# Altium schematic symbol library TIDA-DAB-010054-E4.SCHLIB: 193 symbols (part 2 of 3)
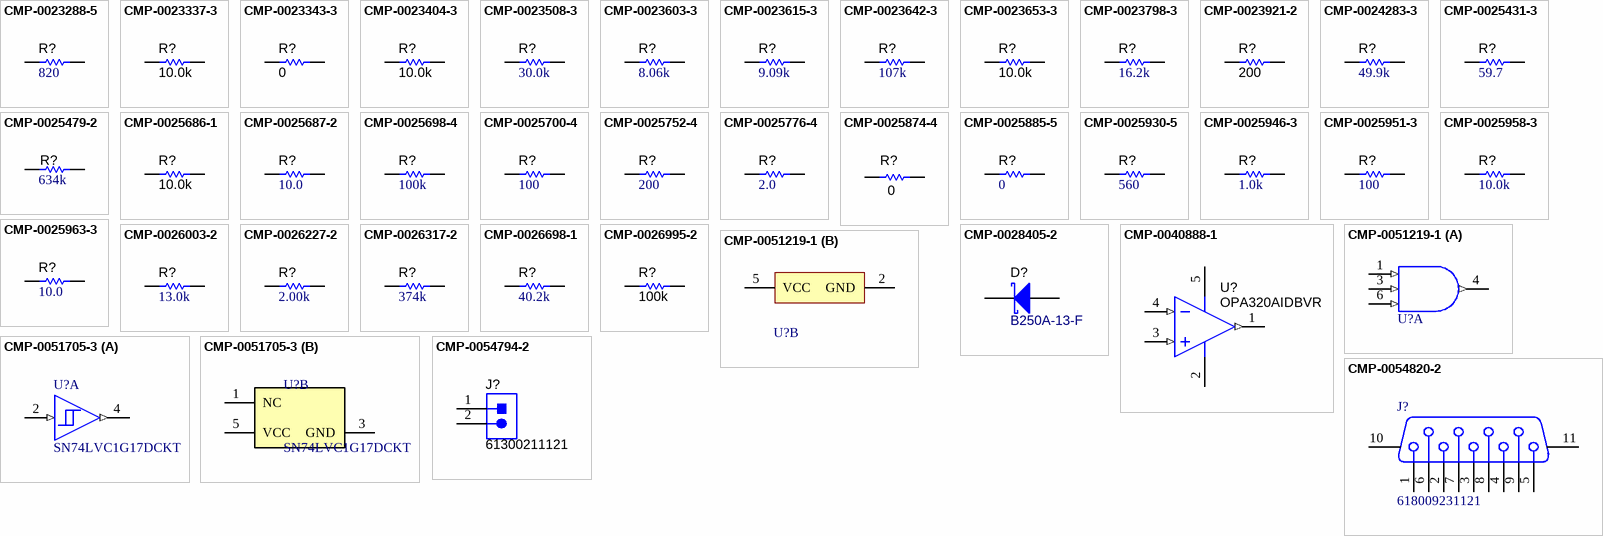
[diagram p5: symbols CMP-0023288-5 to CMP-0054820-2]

## CMP-0023615-3
designator R?, comment ValueDisplayed: 9.09k  (hidden comment: RG1608P-9091-B-T5)
RES, 9.09 k, 0.1%, 0.1 W, 0603; Manufacturer: Susumu Co Ltd; Power_W: 100mW; TempCo: 25 ppm/C; Value_Code: 9k09; U/M: EA; Value: 9.09k; EIA_Code: E192; SizeX_mm: 1.6; SizeY_mm: 0.8; SizeZ_mm: 1; Value2: 0.1W; SizeArea_mm2: 1.28; CompType: Resistor; VDC_V: 75V; AEC Category: Q200
footprint 0603 (0603 from SM-752 data)
footprint 0603_HV (Ernesto recommended land pattern.  26 mil between pads.)
footprint 0603L (0603 from SM-752 data)
footprint 0603S
footprint 0603M (0603 from SM-752 data)
pins: 1, 2

## CMP-0023642-3
designator R?, comment ValueDisplayed: 107k  (hidden comment: RT0603BRD07107KL)
RES, 107 k, 0.1%, 0.1 W, 0603; Manufacturer: Yageo America; Power_W: 100mW; TempCo: 25 ppm/C; U/M: EA; Value: 107k; EIA_Code: E192; SizeX_mm: 1.6; SizeY_mm: 0.8; SizeZ_mm: 1; Value2: 0.1W; SizeArea_mm2: 1.28; CompType: Resistor; VDC_V: 75V; AEC Category: Q200
footprint 0603 (0603 from SM-752 data)
footprint 0603_HV (Ernesto recommended land pattern.  26 mil between pads.)
footprint 0603L (0603 from SM-752 data)
footprint 0603S
footprint 0603M (0603 from SM-752 data)
pins: 1, 2

## CMP-0023653-3
designator R?, comment ValueDisplayed: 10.0k  (hidden comment: RT0603BRD0710KL)
RES, 10.0 k, 0.1%, 0.1 W, 0603; Manufacturer: Yageo America; Manufacturer: Yageo; Power_W: 100mW; TempCo: 25 ppm/C; Value_Code: 10k0; U/M: EA; Value: 10.0k; EIA_Code: E192; Res_ohm: 10k; SizeX_mm: 1.6; SizeY_mm: 0.8; SizeZ_mm: 1; Value2: 0.1W; SizeArea_mm2: 1.28; CompType: Resistor; VDC_V: 75V; AEC Category: Q200
footprint 0603 (0603 from SM-752 data)
footprint 0603_HV (Ernesto recommended land pattern.  26 mil between pads.)
footprint 0603L (0603 from SM-752 data)
footprint 0603S
footprint 0603M (0603 from SM-752 data)
pins: 1, 2

## CMP-0023798-3
designator R?, comment ValueDisplayed: 16.2k  (hidden comment: RT0603BRD0716K2L)
RES, 16.2 k, 0.1%, 0.1 W, 0603; Manufacturer: Yageo America; Power_W: 100mW; TempCo: 25 ppm/C; Value_Code: 16k2; U/M: EA; Value: 16.2k; EIA_Code: E192; SizeX_mm: 1.6; SizeY_mm: 0.8; SizeZ_mm: 1; Value2: 0.1W; SizeArea_mm2: 1.28; CompType: Resistor; VDC_V: 75V; AEC Category: Q200
footprint 0603 (0603 from SM-752 data)
footprint 0603_HV (Ernesto recommended land pattern.  26 mil between pads.)
footprint 0603L (0603 from SM-752 data)
footprint 0603S
footprint 0603M (0603 from SM-752 data)
pins: 1, 2

## CMP-0023921-2
designator R?, comment ValueDisplayed: 200  (hidden comment: RT0603BRD07200RL)
RES, 200, 0.1%, 0.1 W, 0603; Manufacturer: Yageo America; Power_W: 100mW; TempCo: 25 ppm/C; Value_Code: 200R; U/M: EA; Value: 200; EIA_Code: E192; SizeX_mm: 1.6; SizeY_mm: 0.8; SizeZ_mm: 1; Value2: 0.1W; SizeArea_mm2: 1.28; CompType: Resistor; VDC_V: 75V; AEC Category: Q200
footprint 0603 (0603 from SM-752 data)
footprint 0603_HV (Ernesto recommended land pattern.  26 mil between pads.)
footprint 0603L (0603 from SM-752 data)
footprint 0603S
footprint 0603M (0603 from SM-752 data)
pins: 1, 2

## CMP-0024283-3
designator R?, comment ValueDisplayed: 49.9k  (hidden comment: RT0603BRD0749K9L)
RES, 49.9 k, 0.1%, 0.1 W, 0603; Manufacturer: Yageo America; Power_W: 100mW; TempCo: 25 ppm/C; Value_Code: 49k9; U/M: EA; Value: 49.9k; EIA_Code: E192; SizeX_mm: 1.6; SizeY_mm: 0.8; SizeZ_mm: 1; Value2: 0.1W; SizeArea_mm2: 1.28; CompType: Resistor; VDC_V: 75V; AEC Category: Q200
footprint 0603 (0603 from SM-752 data)
footprint 0603_HV (Ernesto recommended land pattern.  26 mil between pads.)
footprint 0603L (0603 from SM-752 data)
footprint 0603S
footprint 0603M (0603 from SM-752 data)
pins: 1, 2

## CMP-0025431-3
designator R?, comment ValueDisplayed: 59.7  (hidden comment: RT0603DRE0759R7L)
RES, 59.7, 0.5%, 0.1 W, 0603; Manufacturer: Yageo America; Power_W: 100mW; TempCo: 50 ppm/C; Value_Code: 59R7; U/M: EA; Value: 59.7; EIA_Code: E192; SizeX_mm: 1.6; SizeY_mm: 0.8; SizeZ_mm: 1; Value2: 0.1W; SizeArea_mm2: 1.28; CompType: Resistor; VDC_V: 75V; AEC Category: Q200
footprint 0603 (0603 from SM-752 data)
footprint 0603_HV (Ernesto recommended land pattern.  26 mil between pads.)
footprint 0603L (0603 from SM-752 data)
footprint 0603S
footprint 0603M (0603 from SM-752 data)
pins: 1, 2

## CMP-0025479-2
designator R?, comment ValueDisplayed: 634k  (hidden comment: RT0603DRE07634KL)
RES, 634 k, 0.5%, 0.1 W, 0603; Manufacturer: Yageo America; Power_W: 100mW; TempCo: 50 ppm/C; U/M: EA; Value: 634k; EIA_Code: E192; SizeX_mm: 1.6; SizeY_mm: 0.8; SizeZ_mm: 1; Value2: 0.1W; SizeArea_mm2: 1.28; CompType: Resistor; VDC_V: 75V; AEC Category: Q200
footprint 0603 (0603 from SM-752 data)
footprint 0603_HV (Ernesto recommended land pattern.  26 mil between pads.)
footprint 0603L (0603 from SM-752 data)
footprint 0603S
footprint 0603M (0603 from SM-752 data)
pins: 1, 2

## CMP-0025686-1
designator R?, comment ValueDisplayed: 10.0k  (hidden comment: TNPW060310K0BEEA)
RES, 10.0 k, 0.1%, 0.1 W, AEC-Q200 Grade 1, 0603; Manufacturer: Vishay-Dale; Power_W: 100mW; TempCo: 25 ppm/C; Value_Code: 10k0; U/M: EA; Value: 10.0k; EIA_Code: E192; Res_ohm: 10k; SizeX_mm: 1.6; SizeY_mm: 0.85; SizeZ_mm: 0.55; Value2: 0.1W; SizeArea_mm2: 1.36; CompType: Resistor; AEC Qualified: Y; VDC_V: 75V; AEC Grade: 1; AEC Category: Q200
footprint TNPW0603 (Vishay)
pins: 1, 2

## CMP-0025687-2
designator R?, comment ValueDisplayed: 10.0  (hidden comment: TNPW060310R0BEEA)
RES, 10.0, 0.1%, 0.1 W, 0603; Manufacturer: Vishay-Dale; Power_W: 100mW; TempCo: 25 ppm/C; Value_Code: 10R0; U/M: EA; Value: 10.0; EIA_Code: E192; Res_ohm: 10; SizeX_mm: 1.6; SizeY_mm: 0.8; SizeZ_mm: 1; Value2: 0.1W; SizeArea_mm2: 1.28; CompType: Resistor; VDC_V: 75V; AEC Category: Q200
footprint 0603 (0603 from SM-752 data)
footprint 0603_HV (Ernesto recommended land pattern.  26 mil between pads.)
footprint 0603L (0603 from SM-752 data)
footprint 0603S
footprint 0603M (0603 from SM-752 data)
pins: 1, 2

## CMP-0025698-4
designator R?, comment ValueDisplayed: 100k  (hidden comment: CRCW0603100KJNEA)
RES, 100 k, 5%, 0.1 W, AEC-Q200 Grade 0, 0603; Manufacturer: Vishay-Dale; Manufacturer: Vishay/Dale; Power_W: 100mW; TempCo: 200 ppm/C; Value: 100k; EIA_Code: E24; SizeX_mm: 1.6; SizeY_mm: 0.8; SizeZ_mm: 1; Value2: 0.1W; SizeArea_mm2: 1.28; CompType: Resistor; AEC Qualified: Y; VDC_V: 75V; AEC Category: Q200; AEC Grade: 0
footprint 0603 (0603 from SM-752 data)
footprint 0603_HV (Ernesto recommended land pattern.  26 mil between pads.)
footprint 0603L (0603 from SM-752 data)
footprint 0603S
footprint 0603M (0603 from SM-752 data)
pins: 1, 2

## CMP-0025700-4
designator R?, comment ValueDisplayed: 100  (hidden comment: CRCW0603100RJNEA)
RES, 100, 5%, 0.1 W, AEC-Q200 Grade 0, 0603; Manufacturer: Vishay-Dale; Power_W: 100mW; TempCo: 200 ppm/C; Value_Code: 100R; Value: 100; EIA_Code: E24; SizeX_mm: 1.6; SizeY_mm: 0.8; SizeZ_mm: 1; Value2: 0.1W; SizeArea_mm2: 1.28; CompType: Resistor; AEC Qualified: Y; VDC_V: 75V; AEC Category: Q200; AEC Grade: 0
footprint 0603 (0603 from SM-752 data)
footprint 0603_HV (Ernesto recommended land pattern.  26 mil between pads.)
footprint 0603L (0603 from SM-752 data)
footprint 0603S
footprint 0603M (0603 from SM-752 data)
pins: 1, 2

## CMP-0025752-4
designator R?, comment ValueDisplayed: 200  (hidden comment: CRCW0603200RJNEA)
RES, 200, 5%, 0.1 W, AEC-Q200 Grade 0, 0603; Manufacturer: Vishay-Dale; Manufacturer: Vishay / Dale; Power_W: 100mW; TempCo: 200 ppm/C; Value_Code: 200R; Value: 200; EIA_Code: E24; SizeX_mm: 1.6; SizeY_mm: 0.8; SizeZ_mm: 1; Value2: 0.1W; SizeArea_mm2: 1.28; CompType: Resistor; AEC Qualified: Y; VDC_V: 75V; AEC Category: Q200; AEC Grade: 0
footprint 0603 (0603 from SM-752 data)
footprint 0603_HV (Ernesto recommended land pattern.  26 mil between pads.)
footprint 0603L (0603 from SM-752 data)
footprint 0603S
footprint 0603M (0603 from SM-752 data)
pins: 1, 2

## CMP-0025776-4
designator R?, comment ValueDisplayed: 2.0  (hidden comment: CRCW06032R00JNEA)
RES, 2.0, 5%, 0.1 W, AEC-Q200 Grade 0, 0603; Manufacturer: Vishay-Dale; Power_W: 100mW; TempCo: 200 ppm/C; Value_Code: 2R00; Value: 2.0; EIA_Code: E24; Res_ohm: 2; SizeX_mm: 1.6; SizeY_mm: 0.8; SizeZ_mm: 1; Value2: 0.1W; SizeArea_mm2: 1.28; CompType: Resistor; AEC Qualified: Y; VDC_V: 75V; AEC Category: Q200; AEC Grade: 0
footprint 0603 (0603 from SM-752 data)
footprint 0603_HV (Ernesto recommended land pattern.  26 mil between pads.)
footprint 0603L (0603 from SM-752 data)
footprint 0603S
footprint 0603M (0603 from SM-752 data)
pins: 1, 2

## CMP-0025874-4
designator R?, comment ValueDisplayed: 0  (hidden comment: ERJ-3GEY0R00V)
RES, 0, 5%, 0.1 W, AEC-Q200 Grade 0, 0603; Manufacturer: Panasonic; CompType: Resistor; Value: 0; Value_Code: 0000; Power_W: 100mW; Value2: 0.1W; VDC_V: 50V; TempCo: 600 ppm/C; SizeArea_mm2: 1.28; SizeX_mm: 1.6; SizeY_mm: 0.8; SizeZ_mm: 1; EIA_Code: E24; AEC Category: Q200; AEC Qualified: Y; SizeAreaWB_mm2: 4.68
footprint 0603 (0603 from SM-752 data)
footprint 0603M (0603 from SM-752 data)
footprint 0603L (0603 from SM-752 data)
footprint 0603_HV (Ernesto recommended land pattern.  26 mil between pads.)
footprint 0603S
pins: 1, 2

## CMP-0025885-5
designator R?, comment ValueDisplayed: 0  (hidden comment: RC0603JR-070RL)
RES, 0, 5%, 0.1 W, 0603; Manufacturer: Yageo; Power_W: 100mW; TempCo: 200 ppm/C; Value_Code: 0000; Value: 0; EIA_Code: E24; SizeX_mm: 1.6; SizeZ_mm: 1; Value2: 0.1W; SizeArea_mm2: 1.28; CompType: Resistor; AEC Qualified: N; VDC_V: 75V; AEC Category: Q200; SizeY_mm: 0.8; SizeAreaWB_mm2: 4.68
footprint 0603 (0603 from SM-752 data)
footprint 0603_HV (Ernesto recommended land pattern.  26 mil between pads.)
footprint 0603L (0603 from SM-752 data)
footprint 0603S
footprint 0603M (0603 from SM-752 data)
pins: 1, 2

## CMP-0025930-5
designator R?, comment ValueDisplayed: 560  (hidden comment: RC0603JR-07560RL)
RES, 560, 5%, 0.1 W, 0603; Manufacturer: Yageo; Power_W: 100mW; TempCo: 100 ppm/C; Value_Code: 560R; Value: 560; EIA_Code: E24; SizeX_mm: 1.6; SizeY_mm: 0.8; SizeZ_mm: 1; Value2: 0.1W; SizeArea_mm2: 1.28; CompType: Resistor; AEC Qualified: N; VDC_V: 75V; AEC Category: Q200; SizeAreaWB_mm2: 4.68
footprint 0603 (0603 from SM-752 data)
footprint 0603_HV (Ernesto recommended land pattern.  26 mil between pads.)
footprint 0603L (0603 from SM-752 data)
footprint 0603S
footprint 0603M (0603 from SM-752 data)
pins: 1, 2

## CMP-0025946-3
designator R?, comment ValueDisplayed: 1.0k  (hidden comment: RCA06031K00JNEA)
RES, 1.0 k, 5%, 0.1 W, AEC-Q200 Grade 0, 0603; Manufacturer: Vishay-Dale; Manufacturer: Vishay / Dale; Power_W: 100mW; TempCo: 200 ppm/C; Value_Code: 1k00; U/M: EA; Value: 1.0k; EIA_Code: E24; Res_ohm: 1k; SizeX_mm: 1.6; SizeY_mm: 0.8; SizeZ_mm: 1; Value2: 0.1W; SizeArea_mm2: 1.28; CompType: Resistor; AEC Qualified: Y; VDC_V: 75V; AEC Grade: 0; AEC Category: Q200
footprint 0603 (0603 from SM-752 data)
footprint 0603_HV (Ernesto recommended land pattern.  26 mil between pads.)
footprint 0603L (0603 from SM-752 data)
footprint 0603S
footprint 0603M (0603 from SM-752 data)
pins: 1, 2

## CMP-0025951-3
designator R?, comment ValueDisplayed: 100  (hidden comment: CRCW0402100RFKED)
RES, 100, 1%, 0.063 W, AEC-Q200 Grade 0, 0402; Manufacturer: Vishay-Dale; Manufacturer: Vishay / Dale; Power_W: 63mW; TempCo: 100 ppm/C; Value_Code: 100R; Value: 100; EIA_Code: E96; SizeX_mm: 1; SizeY_mm: 0.5; SizeZ_mm: 0.6; Value2: 0.063W; CompType: Resistor; AEC Qualified: Y; VDC_V: 50V; AEC Category: Q200; AEC Grade: 0
footprint 0402 (0402 from SM-752 data)
footprint 0402S (Based on C0402S footprint from PADS legacy)
footprint 0402L (0402 from SM-752 data)
footprint 0402M (0402 from SM-752 data)
pins: 1, 2

## CMP-0025958-3
designator R?, comment ValueDisplayed: 10.0k  (hidden comment: CRCW040210K0FKED)
RES, 10.0 k, 1%, 0.063 W, AEC-Q200 Grade 0, 0402; Manufacturer: Vishay-Dale; Manufacturer: Vishay / Dale; Power_W: 63mW; TempCo: 100 ppm/C; Value_Code: 10k0; Value: 10.0k; EIA_Code: E96; Res_ohm: 10k; SizeX_mm: 1; SizeY_mm: 0.5; SizeZ_mm: 0.6; Value2: 0.063W; CompType: Resistor; AEC Qualified: Y; VDC_V: 50V; AEC Category: Q200; AEC Grade: 0
footprint 0402 (0402 from SM-752 data)
footprint 0402S (Based on C0402S footprint from PADS legacy)
footprint 0402L (0402 from SM-752 data)
footprint 0402M (0402 from SM-752 data)
pins: 1, 2

## CMP-0025963-3
designator R?, comment ValueDisplayed: 10.0  (hidden comment: CRCW040210R0FKED)
RES, 10.0, 1%, 0.063 W, AEC-Q200 Grade 0, 0402; Manufacturer: Vishay-Dale; Manufacturer: Vishay / Dale; Power_W: 63mW; TempCo: 100 ppm/C; Value_Code: 10R0; Value: 10.0; EIA_Code: E96; Res_ohm: 10; SizeX_mm: 1; SizeY_mm: 0.5; SizeZ_mm: 0.6; Value2: 0.063W; CompType: Resistor; AEC Qualified: Y; VDC_V: 50V; AEC Category: Q200; AEC Grade: 0
footprint 0402 (0402 from SM-752 data)
footprint 0402S (Based on C0402S footprint from PADS legacy)
footprint 0402L (0402 from SM-752 data)
footprint 0402M (0402 from SM-752 data)
pins: 1, 2

## CMP-0026003-2
designator R?, comment ValueDisplayed: 13.0k  (hidden comment: CRCW040213K0FKED)
RES, 13.0 k, 1%, 0.063 W, 0402; Manufacturer: Vishay-Dale; Manufacturer: Vishay / Dale; Power_W: 63mW; TempCo: 100 ppm/C; Value_Code: 13k0; U/M: EA; Value: 13.0k; EIA_Code: E96; Res_ohm: 13k; SizeX_mm: 1; SizeY_mm: 0.5; SizeZ_mm: 0.6; Value2: 0.063W; CompType: Resistor; VDC_V: 50V; AEC Category: Q200
footprint 0402 (0402 from SM-752 data)
footprint 0402S (Based on C0402S footprint from PADS legacy)
footprint 0402L (0402 from SM-752 data)
footprint 0402M (0402 from SM-752 data)
pins: 1, 2

## CMP-0026227-2
designator R?, comment ValueDisplayed: 2.00k  (hidden comment: CRCW04022K00FKED)
RES, 2.00 k, 1%, 0.063 W, AEC-Q200 Grade 0, 0402; Manufacturer: Vishay-Dale; Power_W: 63mW; TempCo: 100 ppm/C; Value_Code: 2k00; Value: 2.00k; EIA_Code: E96; Res_ohm: 2k; SizeX_mm: 1; SizeY_mm: 0.5; SizeZ_mm: 0.6; Value2: 0.063W; CompType: Resistor; AEC Qualified: Y; VDC_V: 50V; AEC Category: Q200; AEC Grade: 0
footprint 0402 (0402 from SM-752 data)
footprint 0402S (Based on C0402S footprint from PADS legacy)
footprint 0402L (0402 from SM-752 data)
footprint 0402M (0402 from SM-752 data)
pins: 1, 2

## CMP-0026317-2
designator R?, comment ValueDisplayed: 374k  (hidden comment: CRCW0402374KFKED)
RES, 374 k, 1%, 0.063 W, AEC-Q200 Grade 0, 0402; Manufacturer: Vishay-Dale; Power_W: 63mW; TempCo: 100 ppm/C; Value: 374k; EIA_Code: E96; SizeX_mm: 1; SizeY_mm: 0.5; SizeZ_mm: 0.6; Value2: 0.063W; CompType: Resistor; AEC Qualified: Y; VDC_V: 50V; AEC Category: Q200; AEC Grade: 0
footprint 0402 (0402 from SM-752 data)
footprint 0402S (Based on C0402S footprint from PADS legacy)
footprint 0402L (0402 from SM-752 data)
footprint 0402M (0402 from SM-752 data)
pins: 1, 2

## CMP-0026698-1
designator R?, comment ValueDisplayed: 40.2k  (hidden comment: ERJ-2RKF4022X)
RES, 40.2 k, 1%, 0.1 W, AEC-Q200 Grade 0, 0402; Manufacturer: Panasonic; Power_W: 100mW; TempCo: 100 ppm/C; Value_Code: 40k2; U/M: EA; Value: 40.2k; EIA_Code: E96; SizeX_mm: 1; SizeY_mm: 0.5; SizeZ_mm: 0.6; Value2: 0.1W; CompType: Resistor; AEC Qualified: Y; VDC_V: 50V; AEC Grade: 0; AEC Category: Q200
footprint 0402 (0402 from SM-752 data)
footprint 0402S (Based on C0402S footprint from PADS legacy)
footprint 0402L (0402 from SM-752 data)
footprint 0402M (0402 from SM-752 data)
pins: 1, 2

## CMP-0026995-2
designator R?, comment ValueDisplayed: 100k  (hidden comment: ERJ-2GEJ104X)
RES, 100 k, 5%, 0.1 W, AEC-Q200 Grade 0, 0402; Manufacturer: Panasonic; Power_W: 100mW; TempCo: 200 ppm/C; U/M: EA; Value: 100k; EIA_Code: E24; SizeX_mm: 1; SizeY_mm: 0.5; SizeZ_mm: 0.6; Value2: 0.1W; CompType: Resistor; AEC Qualified: Y; VDC_V: 50V; AEC Grade: 0; AEC Category: Q200
footprint 0402 (0402 from SM-752 data)
footprint 0402S (Based on C0402S footprint from PADS legacy)
footprint 0402L (0402 from SM-752 data)
footprint 0402M (0402 from SM-752 data)
pins: 1, 2

## CMP-0028405-2
designator D?, comment B250A-13-F
Diode, Schottky, 50 V, 2 A, SMA; Manufacturer: Diodes Inc.; Manufacturer: Diodes; SizeArea_mm2: 16.3228; RJC_CperW: 20; Vr_V: 50V; SizeX_mm: 5.59; Green_REACh: Incomplete; SizeY_mm: 2.92; Green_Lifecycle: Not Set; Value2: 0.7V; Io_A: 2A; Value: 50V; SizeZ_mm: 2.87; SizeAreaWB_mm2: 37.3428; AEC Category: Q101; TJmax_C: 150°C; Vf_V: 700mV
footprint SMA (Molded Diode, 2-Leads, Body 4.3x2.6mm, IPC Medium Density, based on OnSemi component dimensions and land pattern)
pins: 1 K, 2 A

## CMP-0040888-1
designator U?, comment OPA320AIDBVR
Precision, 20 MHz, 0.9 pA Ib, RRIO, CMOS Operational Amplifier, 1.8 to 5.5 V, -40 to 125 degC, 5-pin SOT23 (DBV5), Green (RoHS & no Sb/Br); Manufacturer: Texas Instruments; CMRR(Min)(dB): 100; Iq per channel(Max)(mA): 1.75; IIB(Max)(pA): 0.9; Total Supply Voltage(Min)(+5V is 5, +/-5V is 10): 1.8; Sub Family: High Output Current Amplifier (>=50mA), Low Input Bias Current Amp (<=10pA), Low Noise Amp (<=10nV/rtHz), Low Offset Voltage Amplifier (<=500uV), Low Supply Voltage Amplifier (<=2.7V), Precision Amplifier; Number of Channels: 2; Total Supply Voltage(Max)(+5V is 5, +/-5V is 10): 5.5; Offset Drift(Typ)(uV/C): 1.5; Vn at 1kHz(Typ)(nV/rtHz): 8.5; Slew Rate(Typ)(V/us): 10; Vio (25C)(Max)(mV): 0.15
footprint DBV0005A_N (SOT23, 5-Leads, Body 2.9x1.6mm, Pitch 0.95mm, Lead Span 2.8mm, IPC Medium Density)
footprint DBV0005A_M (SOT23, 5-Leads, Body 2.9x1.6mm, Pitch 0.95mm, Lead Span 2.8mm, IPC Low Density)
footprint DBV0005A_L (SOT23, 5-Leads, Body 2.9x1.6mm, Pitch 0.95mm, Lead Span 2.8mm, IPC High Density)
pins: 1 OUT (out), 2 V- (power), 3 IN+ (in), 4 IN- (in), 5 V+ (power)

## CMP-0051219-1
designator U?, comment SN74LVC1G11DBVR  (value not drawn)
Single 3-Input Positive-AND Gate, DBV0006A, LARGE T&R; Manufacturer: Texas Instruments; Output Type: CMOS; Voltage(Nom)(V): 1.8,2.5,3.3,5; ICC @ Nom Voltage(Max)(mA): 0.01; VCC(Min)(V): 1.65; Output Drive (IOL/IOH)(Max)(mA): 32/-32; Schmitt Trigger: No; Input Type: CMOS/TTL; VCC(Max)(V): 5.5; Gate Type: AND; Rating: Catalog; tpd @ Nom Voltage(Max)(ns): 20,7.8,6.2,4.6; Bits(#): 1; F @ Nom Voltage(Max)(Mhz): 150; Logic: True; Technology Family: LVC
footprint DBV0006A_N (SOT23, 6-Leads, Body 2.9x1.6mm, Pitch 0.95mm, Lead Span 2.8mm, IPC Medium Density)
footprint DBV0006A_M (SOT23, 6-Leads, Body 2.9x1.6mm, Pitch 0.95mm, Lead Span 2.8mm, IPC Low Density)
footprint DBV0006A_L (SOT23, 6-Leads, Body 2.9x1.6mm, Pitch 0.95mm, Lead Span 2.8mm, IPC High Density)
part A pins: 1 A (in), 3 B (in), 4 Y (out), 6 C (in)
part B pins: 2 GND (power), 5 VCC (power)

## CMP-0051705-3
designator U?, comment SN74LVC1G17DCKT
Single Schmitt-Trigger Buffer, DCK0005A, SMALL T&R; Manufacturer: Texas Instruments; Logic: True; Output Type: CMOS; VCC(Max)(V): 5.5; Schmitt Trigger: Yes; Rating: Catalog; Output Drive (IOL/IOH)(Max)(mA): 32/-32; Input Type: CMOS/TTL; ICC @ Nom Voltage(Max)(mA): 0.01; F @ Nom Voltage(Max)(Mhz): 150; Technology Family: LVC; VCC(Min)(V): 1.65; 3-State Output: No; Voltage(Nom)(V): 1.8,2.5,3.3,5; Bits(#): 1; Sub-Family: Non-Inverting Buffer/Driver; tpd @ Nom Voltage(Max)(ns): 11,6.5,5.5,5; AEC Category: Q200; AEC Qualified: N; CompType: IC; SizeAreaWB_mm2: 9.3; SizeArea_mm2: 4.2; SizeX_mm: 2.1; SizeY_mm: 2.0; SizeZ_mm: 1.1
footprint DCK0005A_N (SOT353, 5-Leads, Body 2x1.3mm, Pitch 0.65mm, Lead Span 2.1mm, IPC Medium Density)
footprint DCK0005A_M (SOT353, 5-Leads, Body 2x1.3mm, Pitch 0.65mm, Lead Span 2.1mm, IPC Low Density)
footprint DCK0005A_L (SOT353, 5-Leads, Body 2x1.3mm, Pitch 0.65mm, Lead Span 2.1mm, IPC High Density)
part A pins: 2 A (in) "Input", 4 Y (out) "Output"
part B pins: 1 NC "Ground", 3 GND (power) "Ground Pin", 5 VCC (power) "Power Pin"

## CMP-0054794-2
designator J?, comment 61300211121
Header, 2.54 mm, 2x1, Gold, TH; Manufacturer: Wurth Elektronik; Manufacturer: Wurth Electronics; Shrouded: N; Gender: Male; Green_REACh: Passed; Pitch_mm: 2.54; Green_Lifecycle: Active; Row_Count: 1; Cert_UL: Y
footprint WURTH_61300211121 (Header, 2.54mm, 2x1, TH)
pins: 1, 2
1 alternate drawing of the same symbol

## CMP-0054820-2
designator J?, comment 618009231121
Receptacle, D-Sub, 9 Position, R/A, TH; Manufacturer: Wurth Elektronik; Manufacturer: Wurth Electronics; Pitch_mm: 2.77; Gender: Female; Cert_UL: Y; Voltage_V: 125V; ContactFinish: Gold; Row_Count: 2; Current_A: 3A; CNHeader: FALSE; CT: TRUE
footprint Wurth_618009231121 (Receptacle, D-Sub, 9 Position, R/A, TH)
pins: 1, 2, 3, 4, 5, 6, 7, 8, 9, 10, 11

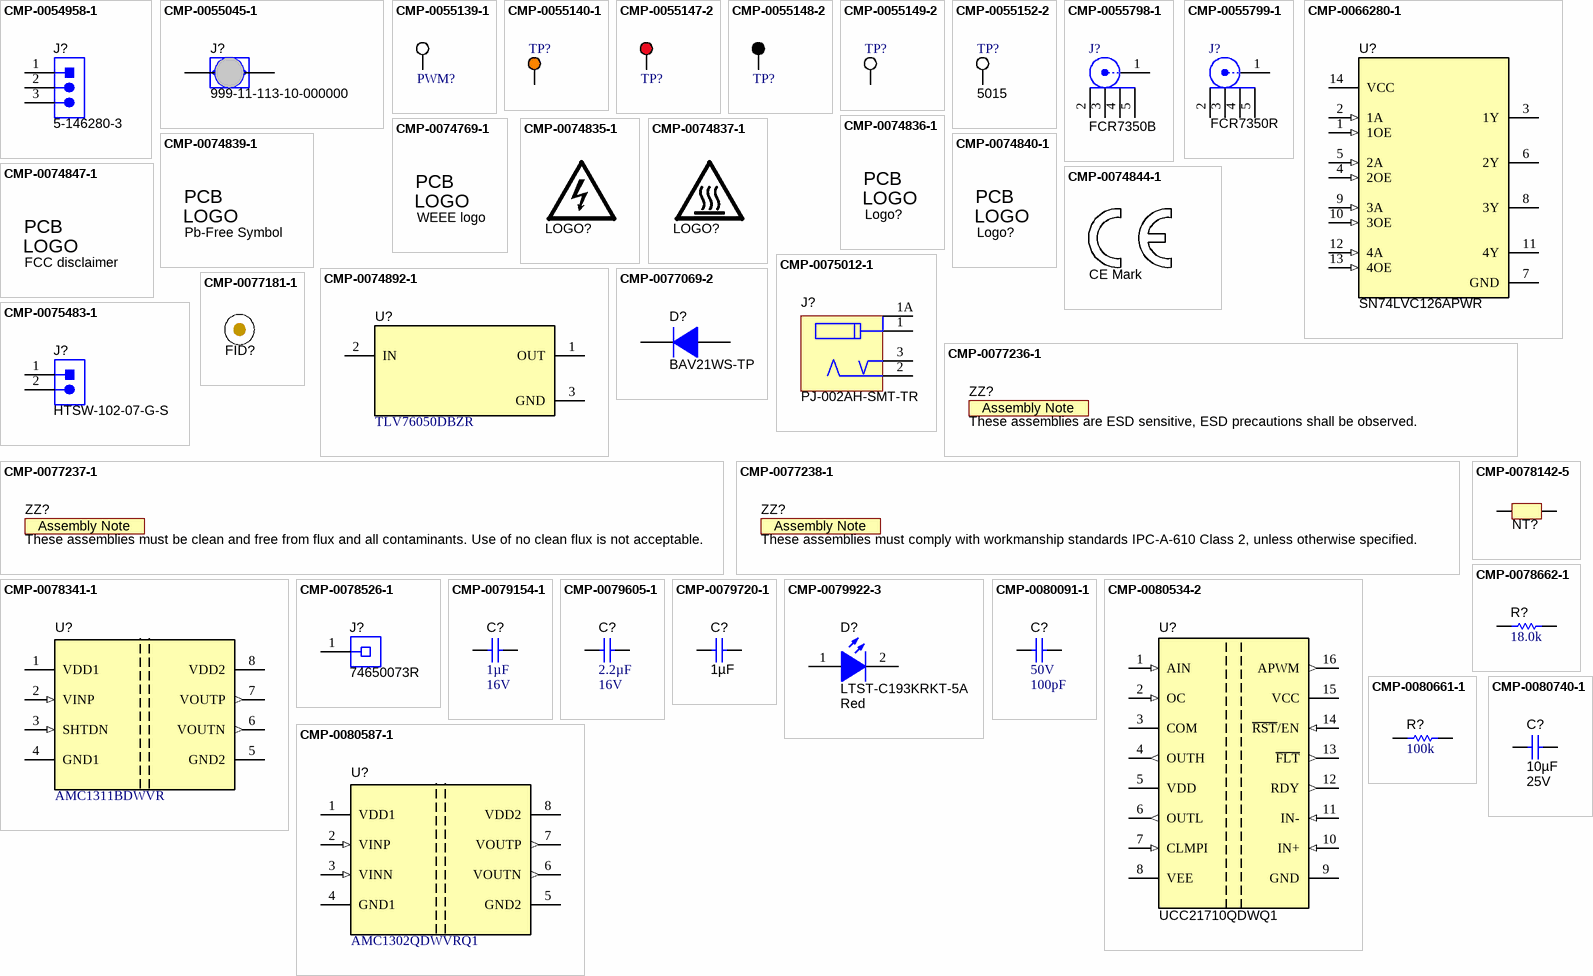
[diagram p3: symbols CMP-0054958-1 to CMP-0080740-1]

## CMP-0054958-1
designator J?, comment 5-146280-3
Header, 2.54mm, 3x1, Gold, TH; Manufacturer: TE Connectivity; CNHeader: TRUE; Green_Lifecycle: Active; Shrouded: N; Gender: Male; Green_REACh: Passed; Row_Count: 1; Pitch_mm: 2.54; CT: FALSE
footprint TE_5-146280-3 (Header, 2.54mm, 3x1, TH)
pins: 1, 2, 3
3 alternate drawings of the same symbol

## CMP-0055045-1
designator J?, comment 999-11-113-10-000000
Shorting Jumper, 7.62mm, 2 Position, Gold, TH; Manufacturer: Mill-Max; CNHeader: FALSE; Gender: Male; Pitch_mm: 7.62; Cert_UL: Y
footprint Mill-Max_999-11-113-10-000000 (Shorting Jumper, 7.62mm, 2 Position, Gold, TH)
pins: 1, 2

## CMP-0055139-1
designator PWM?, comment 5002  (value not drawn)
Test Point, Miniature, White, TH; Manufacturer: Keystone; Manufacturer: Keystone Electronics; ContactFinish: Silver; Green_Lifecycle: Active; Green_REACh: Passed; CNHeader: FALSE; CT: TRUE
footprint Keystone5002 (For Keystone 500x miniature loop terminals)
pins: 1

## CMP-0055140-1
designator TP?, comment 5003  (value not drawn)
Test Point, Miniature, Orange, TH; Manufacturer: Keystone; Manufacturer: Keystone Electronics; CNHeader: FALSE; Green_Lifecycle: Active; Green_REACh: Passed; ContactFinish: Silver; CT: TRUE
footprint Keystone5003 (For Keystone 500x miniature loop terminals)
pins: 1

## CMP-0055147-2
designator TP?, comment 5010  (value not drawn)
Test Point, Multipurpose, Red, TH; Manufacturer: Keystone Electronics; CT: TRUE; ContactFinish: Silver; Green_Lifecycle: Active; CNHeader: FALSE; Green_REACh: Passed
footprint Keystone5010 (Keystone Multipurpose loops)
pins: 1

## CMP-0055148-2
designator TP?, comment 5011  (value not drawn)
Test Point, Multipurpose, Black, TH; Manufacturer: Keystone Electronics; CNHeader: FALSE; ContactFinish: Silver; Green_REACh: Passed; Green_Lifecycle: Active; CT: TRUE
footprint Keystone5011 (Keystone Multipurpose loops)
pins: 1

## CMP-0055149-2
designator TP?, comment 5012  (value not drawn)
Test Point, Multipurpose, White, TH; Manufacturer: Keystone Electronics; ContactFinish: Silver; CT: TRUE; CNHeader: FALSE; Green_Lifecycle: Active; Green_REACh: Passed
footprint Keystone5012 (Keystone Multipurpose loops)
pins: 1

## CMP-0055152-2
designator TP?, comment 5015
Test Point, Miniature, SMT; Manufacturer: Keystone Electronics; CT: TRUE; Green_Lifecycle: Active; Green_REACh: Passed; CNHeader: FALSE
footprint Testpoint_Keystone_Miniature (Miniature SMT test point)
pins: 1

## CMP-0055798-1
designator J?, comment FCR7350B
Panel Socket, 24A, R/A, Gold, TH; Manufacturer: Cliff Electronic Components; CNHeader: FALSE; Gender: Female; Voltage_V: 1kV
footprint Cliff_FCR7350B (Panel Socket, R/A, TH)
pins: 1, 2, 3, 4, 5

## CMP-0055799-1
designator J?, comment FCR7350R
Panel Socket, 24A, R/A, Gold, TH; Manufacturer: Cliff Electronic Components; CNHeader: FALSE; Gender: Female; Voltage_V: 1kV
footprint Cliff_FCR7350R (Panel Socket, R/A, TH)
pins: 1, 2, 3, 4, 5

## CMP-0066280-1
designator U?, comment SN74LVC126APWR
Quadruple Bus Buffer Gate with 3-State Outputs, PW0014A (TSSOP-14); Manufacturer: Texas Instruments; SizeArea_mm2: 32.0; SizeAreaWB_mm2: 58.8; SizeX_mm: 6.4; SizeY_mm: 5.0; SizeZ_mm: 1.2; CompType: IC; U/M: EA
footprint PW0014A_N (TSOP, 14-Leads, Body 5x4.4mm, Pitch 0.65mm, IPC Medium Density)
footprint PW0014A_L (TSOP, 14-Leads, Body 5x4.4mm, Pitch 0.65mm, IPC High Density)
footprint PW0014A_M (TSOP, 14-Leads, Body 5x4.4mm, Pitch 0.65mm, IPC Low Density)
pins: 1 1OE (in), 2 1A (in), 3 1Y (hiz), 4 2OE (in), 5 2A (in), 6 2Y (hiz), 7 GND (power), 8 3Y (hiz), 9 3A (in), 10 3OE (in), 11 4Y (hiz), 12 4A (in), 13 4OE (in), 14 VCC (power)

## CMP-0074769-1
designator Logo?, comment WEEE logo  (no BOM)
footprint WEEE_Minimum (WEEElie bin)

## CMP-0074835-1
designator LOGO?, comment DANGER HIGH VOLTAGE  (value not drawn)  (no BOM)
IEC 61010-1 High Voltage Warning; SymbolCreator: a0412235; Lib Reference: IEC_HighVoltage
footprint IEC_HighVoltage_Large
footprint IEC_HighVoltage_Small
footprint IEC_HighVoltage_Medium

## CMP-0074836-1
designator Logo?, comment CAUTION.  READ USER GUIDE BEFORE USE  (value not drawn)  (no BOM)
IEC 61010-1 Caution Warning; SymbolCreator: a0412235; Lib Reference: IEC_Caution; Library Reference: Logo
footprint IEC_Caution_Large
footprint IEC_Caution_Small
footprint IEC_Caution_Medium

## CMP-0074837-1
designator LOGO?, comment CAUTION HOT SURFACE  (value not drawn)  (no BOM)
IEC 61010-1 Hot Surface Warning; SymbolCreator: a0412235; Lib Reference: IEC_HotSurface
footprint IEC_HotSurface_Large
footprint IEC_HotSurface_Small
footprint IEC_HotSurface_Medium

## CMP-0074839-1
designator Logo?, comment Pb-Free Symbol  (no BOM)
SymbolCreator: a0412235; Library Reference: Logo
footprint Pb-Free_Overlay_Medium
footprint Pb-Free_Overlay_Small

## CMP-0074840-1
designator Logo?, comment ESD Susceptible  (value not drawn)  (no BOM)
ESD Susceptible Symbol; SymbolCreator: a0412235; Lib Reference: ESD_Susceptible; Library Reference: Logo
footprint ESD_Overlay_Large
footprint ESD_Overlay_Small
footprint ESD_Overlay_Medium

## CMP-0074844-1
designator Logo?, comment CE Mark  (no BOM)
SymbolCreator: a0412235
footprint CE_Mark_5mm (Minimum text height for CE Mark)
footprint CE_Mark_10mm (Double the minimum text height for CE Mark)

## CMP-0074847-1
designator Logo?, comment FCC disclaimer  (no BOM)
FCC_disclaimer; Library Reference: Logo
footprint FCC_disclaimer
footprint FCC_disclaimer_stacked

## CMP-0074892-1
designator U?, comment TLV76050DBZR
100-mA, 30-V, Fixed-Output, Linear-Voltage Regulator, DBZ0003A (SOT-23-3); Alternate PartNumber: TLV76050DBZT; Alternate Manufacturer: Texas Instruments; SizeAreaWB_mm2: 14.0; SizeZ_mm: 1.12; SizeX_mm: 2.5; SizeY_mm: 3.0; SizeArea_mm2: 7.5; CompType: IC; AEC Qualified: N; AEC Category: Q200
footprint DBZ0003A_N (SOT23, 3-Leads, Body 2.9x1.3mm, Pitch 0.95mm, Lead Span 2.4mm, IPC Medium Density)
footprint DBZ0003A_L (SOT23, 3-Leads, Body 2.9x1.3mm, Pitch 0.95mm, Lead Span 2.4mm, IPC High Density)
footprint DBZ0003A_M (SOT23, 3-Leads, Body 2.9x1.3mm, Pitch 0.95mm, Lead Span 2.4mm, IPC Low Density)
pins: 1 OUT (power), 2 IN (power), 3 GND (power)

## CMP-0075012-1
designator J?, comment PJ-002AH-SMT-TR
Power Jack, SMT; Manufacturer: CUI Inc.; Green_Lifecycle: Not Set; Green_REACh: Incomplete; CNHeader: False
footprint CUI_PJ-002AH-SMT (CUI)
pins: 1, 1A, 2, 3

## CMP-0075483-1
designator J?, comment HTSW-102-07-G-S
Header, 100mil, 2x1, Gold, TH; Manufacturer: Samtec; Green_REACh: Passed; CT: False; Green_Lifecycle: Active; CNHeader: True
footprint Samtec_HTSW-102-07-G-S (Samtec 100mil, 1x2, 230 mil above insulator)
pins: 1, 2
1 alternate drawing of the same symbol

## CMP-0077069-2
designator D?, comment BAV21WS-TP
Diode, Standard Recovery Rectifier, 250 V, 0.2 A, SOD-323; Manufacturer: Micro Commercial Components; Manufacturer: MCC; TJmax_C: 150°C; AEC Category: Q101; Green_Lifecycle: Not Set; Value: 250V; Vf_V: 1.25V; SizeZ_mm: 1.0; Value1: 0.2A; SizeX_mm: 2.7; SizeAreaWB_mm2: 8.695; SizeArea_mm2: 3.645; AEC Qualified: N; Io_A: 200mA; SizeY_mm: 1.35; Green_REACh: Incomplete
footprint SOD-323 (NXP recommended land pattern)
pins: 1 K, 2 A

## CMP-0077181-1
designator FID?, comment Fiducial  (value not drawn)
Fiducial mark.  There is nothing to buy or mount.
footprint Fiducial10-30
footprint Fiducial15-30
footprint Fiducial10-20
footprint Fiducial20-40
footprint Fiducial6.4-20

## CMP-0077236-1
designator ZZ?, comment These assemblies are ESD sensitive, ESD precautions shall be observed.  (no BOM)
CompType: AssemblyNote
footprint AssemblyNote (Assembly Note)

## CMP-0077237-1
designator ZZ?, comment These assemblies must be clean and free from flux and all contaminants. Use of no clean flux is not acceptable.  (no BOM)
CompType: AssemblyNote
footprint AssemblyNote (Assembly Note)

## CMP-0077238-1
designator ZZ?, comment These assemblies must comply with workmanship standards IPC-A-610 Class 2, unless otherwise specified.  (no BOM)
CompType: AssemblyNote
footprint AssemblyNote (Assembly Note)

## CMP-0078142-5
designator NT?, comment Net-Tie  (value not drawn)  (net tie, no BOM)
Single point connection between nets.
footprint Net-Tie_0805_HV_NoOverlay (0805_HV pads tied by 10mil copper trace which can be cut.  An 0805 part can be placed on pads.)
footprint Net-Tie_10milWide_30milLong (10mil net tie, no solder mask opening, no solder paste)
footprint NetTie_0402 (Net Tie 0402 size)
footprint Net-Tie_50milWide_30milLong (50mil net tie, no solder mask opening, no solder paste)
footprint Net-Tie_20milWide_60milLong (20mil net tie, no solder mask opening, no solder paste)
footprint Net-Tie_6mil (10mil net tie, no solder mask opening, no solder paste)
footprint NetTie_1206_NoOverlay (1206 pads tied by 10mil copper trace which can be cut.  Part can be placed on pads.)
footprint Net-Tie_0805_HV (0805_HV pads tied by 10mil copper trace which can be cut.  An 0805 part can be placed on pads.)
footprint NetTie_1206 (1206 pads tied by 10mil copper trace which can be cut.  Part can be placed on pads.)
footprint Net-Tie_5milWide_60milLong (5mil net tie, no solder mask opening, no solder paste)
footprint NetTie_0603 (Net Tie 0603 size)
footprint Net-Tie_4x6mil
footprint Net-Tie_6x8mil
footprint Net-Tie_4milsWide_10milsLong (Net-Tie 4 mils wide by 10 mils long)
footprint Net-Tie6milsWide_20milsLong (6 mils wide by 20 mils long)
footprint Net-Tie7milsWide_20milsLong (7 mils wide by 20 mils long)
pins: 1, 2

## CMP-0078341-1
designator U?, comment AMC1311BDWVR
Precision, 2-V Input, Reinforced Isolated Amplifier, DWV0008A (SOIC-8); Alternate Manufacturer: Texas Instruments; SizeAreaWB_mm2: 105.975; SizeZ_mm: 2.8; SizeX_mm: 11.5; SizeY_mm: 5.85; SizeArea_mm2: 67.275; CompType: IC; AEC Qualified: N; AEC Category: Q200
footprint DWV0008A (SOIC, 8-Leads, Body 5.95x7.6mm (max), Pitch 1.27mm)
pins: 1 VDD1 (power), 2 VINP (in), 3 SHTDN (in), 4 GND1 (power), 5 GND2 (power), 6 VOUTN (out), 7 VOUTP (out), 8 VDD2 (power)

## CMP-0078526-1
designator J?, comment 74650073R
Power Element Bush, M3, TH; Manufacturer: Wurth Elektronik; Gender: Female; Current_A: 50A; ContactFinish: Tin; CompType: Screw Terminal
footprint Wurth_WP-THRBU (Power Element Bush, M3, TH)
pins: 1

## CMP-0078662-1
designator R?, comment ValueDisplayed: 18.0k  (hidden comment: ERJ3EKF1802V)
RES, 18.0 k, 1%, 0.1 W, AEC-Q200 Grade 0, 0603; Manufacturer: Panasonic; Manufacturer Part Number: ERJ-3EKF1802V; Power_W: 100mW; TempCo: 100 ppm/C; Value_Code: 18k0; Value: 18.0k; Res_ohm: 18k; SizeX_mm: 1.6; SizeY_mm: 0.8; SizeZ_mm: 1; Value2: 0.1W; SizeArea_mm2: 1.28; CompType: Resistor; AEC Qualified: Y; AEC Grade: 0; AEC Category: Q200
footprint 0603 (0603 from SM-752 data)
footprint 0603M (0603 from SM-752 data)
footprint 0603L (0603 from SM-752 data)
footprint 0603_HV (Ernesto recommended land pattern.  26 mil between pads.)
footprint 0603S
pins: 1, 2

## CMP-0079154-1
designator C?, comment Cap_F: 1µF  VDC_V: 16V  (hidden comment: GCM188R71C105KA64J)
CAP, CERM, 1 µF, 16 V,+/- 10%, X7R, AEC-Q200 Grade 1, 0603; Manufacturer: MuRata; SizeAreaWB_mm2: 4.68; SizeArea_mm2: 1.28; AEC Qualified: Y; AEC Category: Q200; Value: 1uF; TaMax_C: 125°C; SizeZ_mm: 1; Polarized: N; TaMin_C: -55°C; SizeY_mm: 0.8; U/M: EA; CompType: Capacitor; SizeX_mm: 1.6; Cap_Case: 0603
footprint 0603 (0603 from SM-752 data)
footprint 0603M (0603 from SM-752 data)
footprint 0603L (0603 from SM-752 data)
footprint 0603_HV (Ernesto recommended land pattern.  26 mil between pads.)
footprint 0603S
pins: 1, 2

## CMP-0079605-1
designator C?, comment Cap_F: 2.2µF  VDC_V: 16V  (hidden comment: CC0603KRX7R7BB225)
CAP, CERM, 2.2 µF, 16 V,+/- 10%, X7R, 0603; Manufacturer: Yageo America; Manufacturer: Yageo; TaMin_C: -55°C; Polarized: N; SizeAreaWB_mm2: 4.68; U/M: EA; Value: 2.2uF; TaMax_C: 125°C; SizeZ_mm: 1; SizeX_mm: 1.6; SizeY_mm: 0.8; Cap_Case: 0603; SizeArea_mm2: 1.28; CompType: Capacitor; AEC Category: Q200
footprint 0603 (0603 from SM-752 data)
footprint 0603M (0603 from SM-752 data)
footprint 0603L (0603 from SM-752 data)
footprint 0603_HV (Ernesto recommended land pattern.  26 mil between pads.)
footprint 0603S
pins: 1, 2

## CMP-0079720-1
designator C?, comment Cap_F: 1µF  (hidden comment: GRJ188R71E105KE11D)
CAP, CERM, 1 µF, 25 V,+/- 10%, X7R, 0603; Manufacturer: MuRata; TaMin_C: -55°C; Polarized: N; SizeAreaWB_mm2: 4.68; U/M: EA; Value: 1uF; TaMax_C: 125°C; SizeZ_mm: 1; SizeX_mm: 1.6; SizeY_mm: 0.8; Cap_Case: 0603; Value2: 25V; SizeArea_mm2: 1.28; CompType: Capacitor; AEC Category: Q200
footprint 0603 (0603 from SM-752 data)
footprint 0603M (0603 from SM-752 data)
footprint 0603L (0603 from SM-752 data)
footprint 0603_HV (Ernesto recommended land pattern.  26 mil between pads.)
footprint 0603S
pins: 1, 2

## CMP-0079922-3
designator D?, comment LTST-C193KRKT-5A  value Red
LED, Red, SMD; Manufacturer: Lite-On; Manufacturer: Vishay Lite-On; SizeX_mm: 1.6; Value2: 2V; SizeY_mm: 0.8; Green_REACh: Incomplete; SizeAreaWB_mm2: 4.68; Green_Lifecycle: Not Set; Value1: W; Io_A: 5mA; Type: AlInGaP; SizeZ_mm: 0.45; Tjmax_C: 85°C; SizeArea_mm2: 1.28
footprint LTST-C193_Red (SMD, 2-Leads, Body1.6x0.8mm)
pins: 1 A, 2 K

## CMP-0080091-1
designator C?, comment VDC_V: 50V  ValueDisplayed: 100pF  (hidden comment: C0603C101F5GACTU)
CAP, CERM, 100 pF, 50 V,+/- 1%, C0G/NP0, 0603; Manufacturer: Kemet; SizeAreaWB_mm2: 4.68; SizeArea_mm2: 1.28; AEC Qualified: N; AEC Category: Q200; Value: 100pF; TaMax_C: 125°C; SizeZ_mm: 1; Green_REACh: Passed; TaMin_C: -55°C; SizeY_mm: 0.8; Green_Lifecycle: Active; U/M: EA; CompType: Capacitor; SizeX_mm: 1.6; Cap_Case: 0603
footprint 0603 (0603 from SM-752 data)
footprint 0603M (0603 from SM-752 data)
footprint 0603L (0603 from SM-752 data)
footprint 0603_HV (Ernesto recommended land pattern.  26 mil between pads.)
footprint 0603S
pins: 1, 2

## CMP-0080534-2
designator U?, comment UCC21710QDWQ1
Single Channel Isolated Gate Driver for SiC/IGBT with Advanced Protection and High-CMTI, DW0016B (SOIC-16); Manufacturer: Texas Instruments; Alternate PartNumber: UCC21710QDWRQ1; SizeY_mm: 10.3; CompType: IC; AEC Qualified: Y; SizeArea_mm2: 107.12; SizeAreaWB_mm2: 152.52; SizeZ_mm: 2.65; SizeX_mm: 10.4; AEC Category: Q200
footprint DW0016B_HV (SOIC-16, HV/isolation option)
footprint DW0016B_N (SOIC-16, IPC Medium Density)
footprint DW0016B_M (SOIC-16, IPC Low Density)
footprint DW0016B_L (SOIC-16, IPC High Density)
pins: 1 AIN (in), 2 OC (in), 3 COM (power), 4 OUTH (out), 5 VDD (power), 6 OUTL (out), 7 CLMPI (in), 8 VEE (power), 9 GND (power), 10 IN+ (in), 11 IN- (in), 12 RDY (out), 13 ~{FLT} (out), 14 ~{RST}/EN (in), 15 VCC (power), 16 APWM (out)

## CMP-0080587-1
designator U?, comment AMC1302QDWVRQ1
Precision Reinforced Isolated Amplifier for Current Sensing, DWV0008A (SOIC-8); Alternate Manufacturer: Texas Instruments; SizeAreaWB_mm2: 105.975; SizeZ_mm: 2.8; SizeX_mm: 11.5; SizeY_mm: 5.85; SizeArea_mm2: 67.275; CompType: IC; AEC Qualified: Y; AEC Category: Q200
footprint DWV0008A (SOIC, 8-Leads, Body 5.95x7.6mm (max), Pitch 1.27mm)
pins: 1 VDD1 (power), 2 VINP (in), 3 VINN (in), 4 GND1 (power), 5 GND2 (power), 6 VOUTN (out), 7 VOUTP (out), 8 VDD2 (power)

## CMP-0080661-1
designator R?, comment ValueDisplayed: 100k  (hidden comment: AC0402FR-07100KL)
RES, 100 k, 1%, 0.0625 W, AEC-Q200 Grade 0, 0402; Manufacturer: Yageo America; Manufacturer: Yageo; Power_W: 62.5mW; TempCo: 100 ppm/C; SizeAreaWB_mm2: 3; Value: 100k; EIA_Code: E96; SizeX_mm: 1; SizeY_mm: 0.5; SizeZ_mm: 0.6; CompType: Resistor; AEC Qualified: Y; VDC_V: 50V; AEC Grade: 0; AEC Category: Q200
footprint 0402 (0402 from SM-752 data)
footprint 0402M (0402 from SM-752 data)
footprint 0402L (0402 from SM-752 data)
footprint 0402S (Based on C0402S footprint from PADS legacy)
pins: 1, 2

## CMP-0080740-1
designator C?, comment ValueDisplayed: 10µF  VDC_V: 25V  (hidden comment: C3216X7R1E106K160AB)
CAP, CERM, 10 µF, 25 V,+/- 10%, X7R, 1206; Manufacturer: TDK; Polarized: N; CompType: Capacitor; Value: 10uF; U/M: EA; TaMin_C: -55°C; TaMax_C: 125°C; Cap_Case: 1206; SizeArea_mm2: 5.12; SizeAreaWB_mm2: 10.92; SizeX_mm: 3.2; SizeY_mm: 1.6; SizeZ_mm: 1.8; AEC Category: Q200
footprint 1206_180
footprint 1206_180M (1206_180)
footprint 1206_180L (1206_180)
pins: 1, 2

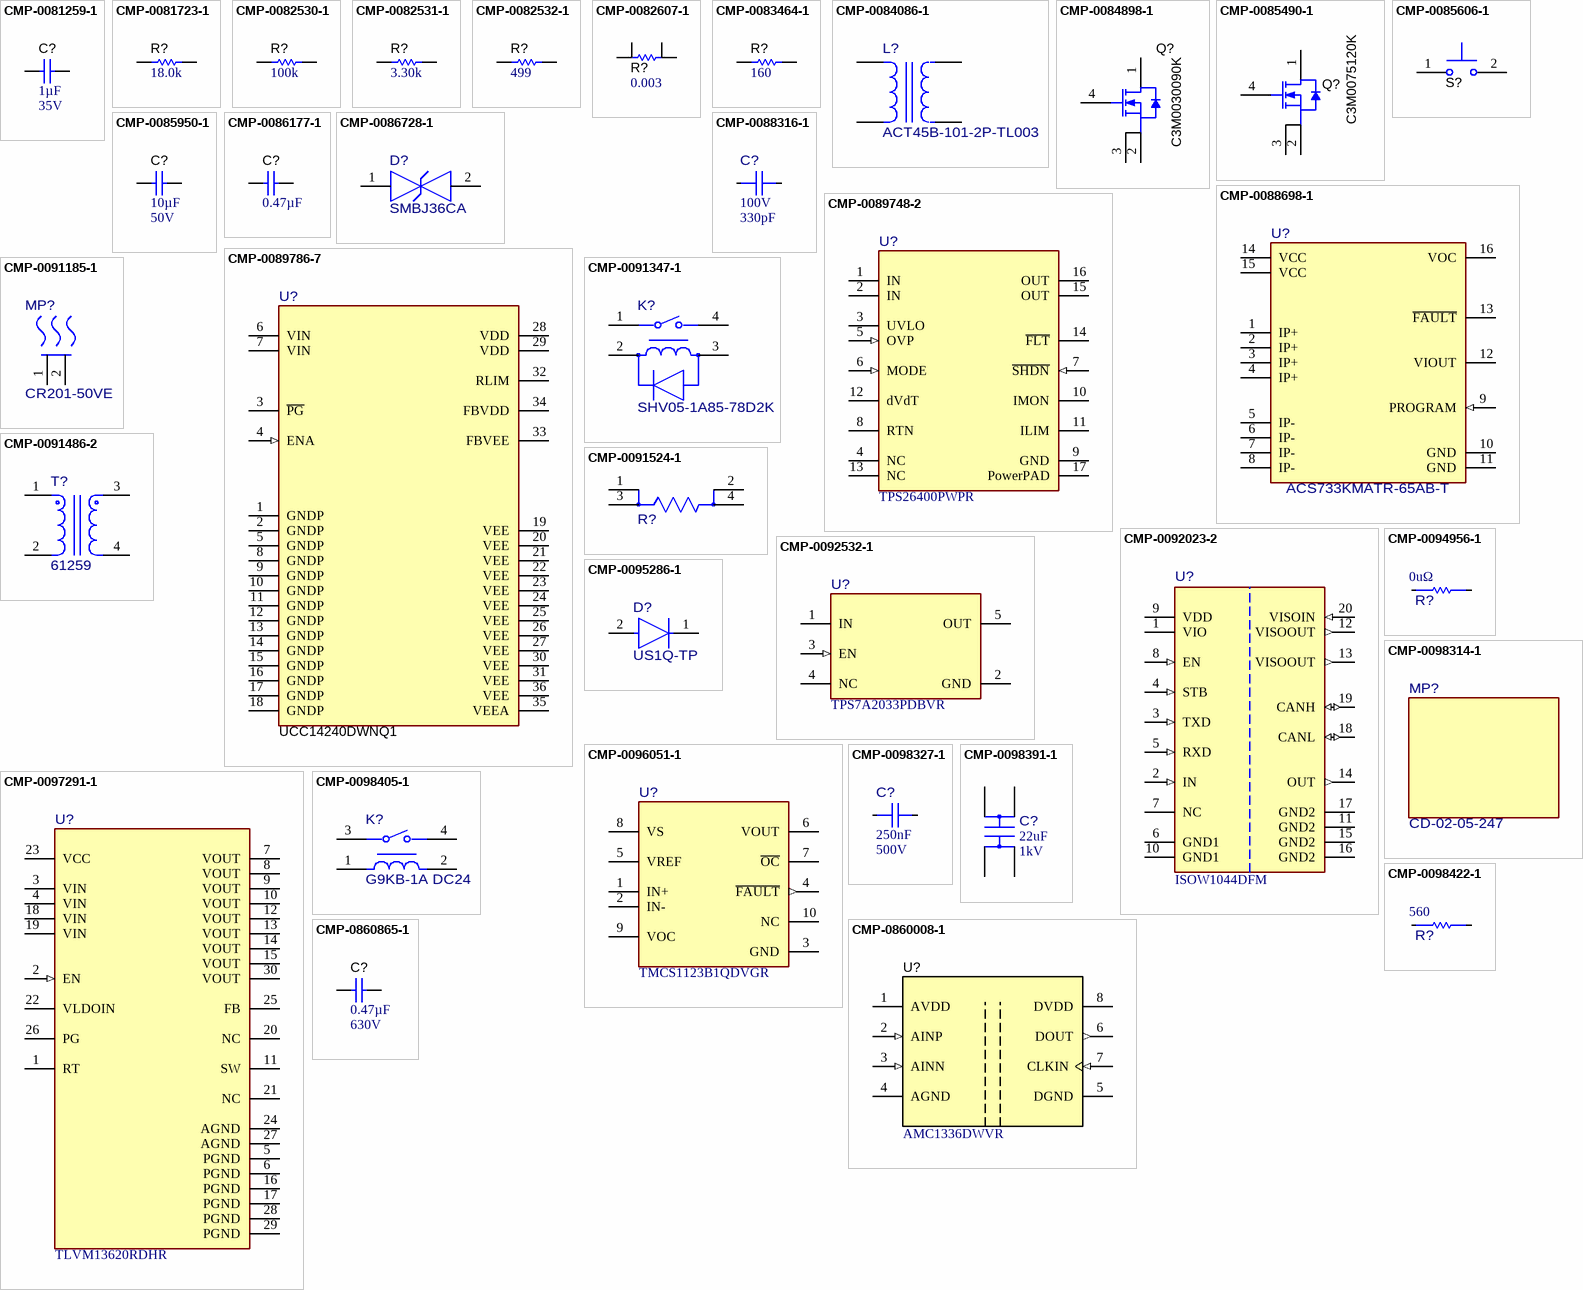
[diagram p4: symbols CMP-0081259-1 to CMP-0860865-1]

## CMP-0081259-1
designator C?, comment Cap_F: 1µF  VDC_V: 35V  (hidden comment: CGA3E1X7R1V105K080AE)
CAP, CERM, 1 µF, 35 V,+/- 10%, X7R, AEC-Q200 Grade 1, 0603; Manufacturer: TDK; SizeAreaWB_mm2: 4.68; SizeArea_mm2: 1.28; AEC Qualified: Y; AEC Category: Q200; Value: 1uF; TaMax_C: 125°C; SizeZ_mm: 1; Polarized: N; TaMin_C: -55°C; SizeY_mm: 0.8; U/M: EA; CompType: Capacitor; SizeX_mm: 1.6; Cap_Case: 0603
footprint 0603 (0603 from SM-752 data)
footprint 0603M (0603 from SM-752 data)
footprint 0603L (0603 from SM-752 data)
footprint 0603_HV (Ernesto recommended land pattern.  26 mil between pads.)
footprint 0603S
pins: 1, 2

## CMP-0081723-1
designator R?, comment ValueDisplayed: 18.0k  (hidden comment: ERJ2RKF1802X)
RES, 18.0 k, 1%, 0.1 W, AEC-Q200 Grade 0, 0402; Manufacturer: Panasonic; Power_W: 100mW; TempCo: 100 ppm/C; SizeAreaWB_mm2: 3; Value_Code: 18k0; Value: 18.0k; Res_ohm: 18k; SizeX_mm: 1; SizeY_mm: 0.5; SizeZ_mm: 0.6; Value2: 0.1W; CompType: Resistor; AEC Qualified: Y; AEC Grade: 0; AEC Category: Q200
footprint 0402 (0402 from SM-752 data)
footprint 0402M (0402 from SM-752 data)
footprint 0402L (0402 from SM-752 data)
footprint 0402S (Based on C0402S footprint from PADS legacy)
pins: 1, 2

## CMP-0082530-1
designator R?, comment ValueDisplayed: 100k  (hidden comment: CRCW0603100KJNEAC)
RES, 100 k, 5%, 0.1 W, 0603; Manufacturer: Vishay-Dale; Manufacturer: Vishay Semiconductors; Power_W: 100mW; TempCo: 200 ppm/C; SizeAreaWB_mm2: 4.68; Value: 100k; EIA_Code: E24; SizeX_mm: 1.6; SizeY_mm: 0.8; SizeZ_mm: 1; Value2: 0.1W; SizeArea_mm2: 1.28; CompType: Resistor; AEC Qualified: N; VDC_V: 75V; AEC Category: Q200
footprint 0603 (0603 from SM-752 data)
footprint 0603M (0603 from SM-752 data)
footprint 0603L (0603 from SM-752 data)
footprint 0603_HV (Ernesto recommended land pattern.  26 mil between pads.)
footprint 0603S
pins: 1, 2

## CMP-0082531-1
designator R?, comment ValueDisplayed: 3.30k  (hidden comment: CRCW06033K30FKEA)
RES, 3.30 k, 1%, 0.1 W, AEC-Q200 Grade 0, 0603; Manufacturer: Vishay-Dale; Manufacturer: Vishay; Power_W: 100mW; TempCo: 100 ppm/C; SizeAreaWB_mm2: 4.68; Value_Code: 3k30; Value: 3.30k; Res_ohm: 3.3k; SizeX_mm: 1.6; SizeY_mm: 0.8; SizeZ_mm: 1; Value2: 0.1W; SizeArea_mm2: 1.28; CompType: Resistor; AEC Qualified: Y; VDC_V: 75V; AEC Grade: 0; AEC Category: Q200
footprint 0603 (0603 from SM-752 data)
footprint 0603M (0603 from SM-752 data)
footprint 0603L (0603 from SM-752 data)
footprint 0603_HV (Ernesto recommended land pattern.  26 mil between pads.)
footprint 0603S
pins: 1, 2

## CMP-0082532-1
designator R?, comment ValueDisplayed: 499  (hidden comment: CRCW0603499RFKEAC)
RES, 499, 1%, 0.1 W, 0603; Manufacturer: Vishay-Dale; Manufacturer: Vishay; Power_W: 100mW; TempCo: 100 ppm/C; SizeAreaWB_mm2: 4.68; Value_Code: 499R; Value: 499; EIA_Code: E96; SizeX_mm: 1.6; SizeY_mm: 0.8; SizeZ_mm: 1; Value2: 0.1W; SizeArea_mm2: 1.28; CompType: Resistor; AEC Qualified: N; VDC_V: 75V; AEC Category: Q200
footprint 0603 (0603 from SM-752 data)
footprint 0603M (0603 from SM-752 data)
footprint 0603L (0603 from SM-752 data)
footprint 0603_HV (Ernesto recommended land pattern.  26 mil between pads.)
footprint 0603S
pins: 1, 2

## CMP-0082607-1
designator R?, comment ValueDisplayed: 0.003  (hidden comment: WSL36373L000FEA)
RES, 0.003, 1%, 3 W, AEC-Q200 Grade 0, 9.14x9.4mm; Manufacturer: Vishay-Dale; Manufacturer: Vishay Dale; Value_Code: 3L000; SizeAreaWB_mm2: 126.996; SizeArea_mm2: 85.916; AEC Qualified: Y; AEC Category: Q200; Res_ohm: 3m; Value: 0.003; SizeZ_mm: 0.889; EIA_Code: E96; TempCo: 50 ppm/C; AEC Grade: 0; Power_W: 3W; SizeY_mm: 9.4; CompType: Resistor; SizeX_mm: 9.14
footprint WSL3637_0_002 (Vishay WSL3637 recommended land pattern for 0.002 to 0.01 Ohm)
pins: 1, 2, 3, 4

## CMP-0083464-1
designator R?, comment ValueDisplayed: 160  (hidden comment: RC1210JR-07160RL)
RES, 160, 5%, 0.5 W, 1210; Manufacturer: Yageo; Power_W: 500mW; TempCo: 100 ppm/C; SizeAreaWB_mm2: 14.7; Value_Code: 160R; Value: 160; EIA_Code: E24; SizeX_mm: 3.2; SizeY_mm: 2.5; SizeZ_mm: 1.35; Value2: 0.5W; SizeArea_mm2: 8; CompType: Resistor; AEC Qualified: N; VDC_V: 200V; AEC Category: Q200
footprint 1210 (1210 from SM-752 data)
footprint 1210M (1210 from SM-752 data)
footprint 1210L (1210 from SM-752 data)
pins: 1, 2

## CMP-0084086-1
designator L?, comment ACT45B-101-2P-TL003
100µH @ 100kHz 2 Line Common Mode Choke Surface Mount 5.8 kOhms @ 10MHz 150mA DCR 2Ohm; Manufacturer: TDK; AEC Grade: Grade 0; Tolerance_%: +50/-30%; AEC Qualified: Yes; Symbol Name: SYM-ACT45B-101-2P-TL003; Ind_H: 100uH; SizeZ_mm: 3mm; DCR_ohm: 2Ω; Impedance At Frequency: 5800Ω @ 10MHz; Imax_A: 0.15A
footprint FP-ACT45B-101-2P-TL003_SMT_4MM5_3MM2-MFG
pins: 1, 2, 3, 4

## CMP-0084898-1
designator Q?, comment C3M0030090K
MOSFET, N-CH, 900 V, 63 A, TO-247-4; Manufacturer: Cree; Alternate Manufacturer: None; ChMode: Enhancement; AEC Category: Q101; AEC Qualified: N; Value2: 87 nC; SizeY_mm: 5.02; SizeZ_mm: 27.97; QgTyp_nC: 87; SizeArea_mm2: 80.0188; SizeAreaWB_mm2: 125.9388; SizeX_mm: 15.94; IdsMax_A: 63A; VdsMax_V: 900V; Vgs_V: 15V; Value1: ? ohm; Value: 900V
footprint TO-247-4 (FM, 4-Leads, Body 15.94x5.02mm, Pitch 2.54mm)
pins: 1 D, 2 S, 3 KS, 4 G

## CMP-0085490-1
designator Q?, comment C3M0075120K
MOSFET, N-CH, 1200 V, 30 A, TO-247-4; Alternate Manufacturer: None; Manufacturer: Cree; Manufacturer: Cree Wolfspeed; VdsMax_V: 1.2kV; ChMode: Enhancement; SizeX_mm: 15.94; SizeY_mm: 5.02; Value2: 51 nC; AEC Qualified: N; Value: 1200V; Value1: ? ohm; QgTyp_nC: 51; IdsMax_A: 30A; AEC Category: Q101; SizeArea_mm2: 80.0188; SizeZ_mm: 27.97; Vgs_V: 19V; SizeAreaWB_mm2: 125.9388
footprint TO-247-4 (FM, 4-Leads, Body 15.94x5.02mm, Pitch 2.54mm)
pins: 1 D, 2 S, 3 KS, 4 G

## CMP-0085606-1
designator S?, comment SKRKAEE020  (value not drawn)
Switch, SPST-NO, 0.05 A, 12 VDC, SMT; Manufacturer: Alps; Manufacturer: Alps Electric; SizeX_mm: 4.8; SizeZ_mm: 2.2; SizeArea_mm2: 13.92; SizeY_mm: 2.9; PositionCount: 1; SizeAreaWB_mm2: 22.62; VDC_V: 12V; CurrentRating_mA: 50A
footprint SW_SKRKAE (SMD, 2-Leads, Body 3.9x2.9mm)
pins: 1, 2

## CMP-0085950-1
designator C?, comment ValueDisplayed: 10µF  VDC_V: 50V  (hidden comment: CGA5L1X7R1H106K160AC)
CAP, CERM, 10 µF, 50 V,+/- 10%, X7R, AEC-Q200 Grade 1, 1206; Manufacturer: TDK; SizeZ_mm: 1.9; Value: 10uF; Cap_Case: 1206; AEC Grade: 1; TaMin_C: -55°C; U/M: EA; CompType: Capacitor; SizeArea_mm2: 5.12; TaMax_C: 125°C; AEC Qualified: Y; AEC Category: Q200; SizeX_mm: 3.2; SizeY_mm: 1.6; Polarized: N; SizeAreaWB_mm2: 10.92
footprint 1206_190
footprint 1206_190M (1206_190)
footprint 1206_190L (1206_190)
pins: 1, 2

## CMP-0086177-1
designator C?, comment ValueDisplayed: 0.47µF  (hidden comment: 2220Y1K00474KETWS2)
CAP, CERM, 0.47 µF, 1000 V,+/- 10%, X7R, AEC-Q200 Grade 1, 2220; Manufacturer: Knowles Capacitors; Manufacturer: Knowles Syfer; Cap_Case: 2220; SizeAreaWB_mm2: 53.9; AEC Category: Q200; TaMax_C: 125°C; SizeArea_mm2: 28.5; SizeX_mm: 5.7; SizeZ_mm: 1.35; Value: 0.47uF; CompType: Capacitor; AEC Qualified: Y; TaMin_C: -55°C; SizeY_mm: 5; Value2: 1000V; AEC Grade: 1; U/M: EA; Cap_F: 470nF; Polarized: N; VDC_V: 1kV
footprint 2220 (Chip Capacitor, Body 5.7x5.0mm, IPC Medium Density)
footprint 2220_M (Chip Capacitor, Body 5.7x5.0mm, IPC Low Density)
footprint 2220_L (Chip Capacitor, Body 5.7x5.0mm, IPC High Density)
pins: 1, 2

## CMP-0086728-1
designator D?, comment SMBJ36CA
Diode TVS Single Bi-Dir 36V 600W 2-Pin SMB; Manufacturer: Littelfuse; SizeZ_mm: 2.61mm; Symbol Name: SYM-SMBJ36CA; Ipp: 10.4µA
footprint FP-SMBJ36CA_DO-214AA-0
pins: 1, 2

## CMP-0088316-1
designator C?, comment VDC_V: 100V  ValueDisplayed: 330pF  (hidden comment: GCM155R72A331KA37D)
330pF ±10% 100V Ceramic Capacitor X7R 0402 (1005 Metric); Manufacturer: Murata; TempCo: 15%; AEC Grade: Grade 1; AEC Qualified: Yes; SizeZ_mm: 0.55mm
footprint FP-GCM155R72A331KA37D_0402-MFG
footprint FP-GCM155R72A331KA37D_0402-IPC_C
footprint FP-GCM155R72A331KA37D_0402-IPC_B
footprint FP-GCM155R72A331KA37D_0402-IPC_A
pins: 1, 2

## CMP-0088698-1
designator U?, comment ACS733KMATR-65AB-T
Manufacturer: Allegro MicroSystems; Sensing Method: Hall Effect; Max Supply Voltage: 3.46V; Coil Resistance: 0.85mΩ; Current Sensitivity: 20.3mV/A; SizeZ_mm: 2.65mm; Max Sensing Current: 65A; Sensor Output: Analog Voltage; TaMax_C: +125°C; Standoff Height: 0.1mm; AEC Qualified: Yes; TaMin_C: -40°C; AEC Grade: Grade 1; Min Supply Voltage: 3.14V; Operating Supply Current: 20mA; TJmax_C: +165°C
footprint FP-ACS733KMATR-65AB-T_SOIC16-MFG
footprint FP-ACS733KMATR-65AB-T_SOIC16-IPC_C
footprint FP-ACS733KMATR-65AB-T_SOIC16-IPC_B
footprint FP-ACS733KMATR-65AB-T_SOIC16-IPC_A
pins: 1 IP+, 2 IP+, 3 IP+, 4 IP+, 5 IP-, 6 IP-, 7 IP-, 8 IP-, 9 PROGRAM (in), 10 GND (power), 11 GND (power), 12 VIOUT, 13 ~{FAULT} (oc), 14 VCC (power), 15 VCC (power), 16 VOC

## CMP-0089748-2
designator U?, comment TPS26400PWPR
42-V, 2-A Industrial eFuse With Integrated Reverse Input Polarity Protection; Manufacturer: Texas Instruments; Number Of Channels: 1; CompType: IC; Max Supply Voltage: 42V; AEC Category: Q200; TJmax_C: +125°C; Standoff Height: 0.05mm; SizeZ_mm: 1.2mm; AEC Qualified: No
footprint PWP0016H-MFG
footprint PWP0016H-IPC_C
footprint PWP0016H-IPC_B
footprint PWP0016H-IPC_A
pins: 1 IN (power), 2 IN (power), 3 UVLO, 4 NC, 5 OVP (in), 6 MODE (in), 7 ~{SHDN} (in), 8 RTN, 9 GND (power), 10 IMON, 11 ILIM, 12 dVdT, 13 NC, 14 ~{FLT} (oc), 15 OUT (power), 16 OUT (power), 17 PowerPAD

## CMP-0089786-7
designator U?, comment UCC14240DWNQ1
2W, 24V-Vin, 25V-Vout, High-Efficiency, >2. 5 kVRMS Isolated DC-DC Converter; Manufacturer: Texas Instruments; Manufacturer Part Number: UCC14240QDWNRQ1; Max Supply Voltage: 27V; Standoff Height: 0.1mm; SizeZ_mm: 3.55mm; AEC Qualified: Yes; Output Voltage: 18-25/2.5-25V; TaMin_C: -40°C; CompType: IC; TJmax_C: +150°C; Min Supply Voltage: 21V; AEC Grade: Grade 1; Number Of Outputs: 2; Output Type: AdjustableProgrammable; TaMax_C: +125°C; AEC Category: Q200
footprint DWN0036-MFG
footprint DWN0036-IPC_C
footprint DWN0036-IPC_B
footprint DWN0036-IPC_A
pins: 1 GNDP (power), 2 GNDP (power), 3 ~{PG} (oc), 4 ENA (in), 5 GNDP (power), 6 VIN (power), 7 VIN (power), 8 GNDP (power), 9 GNDP (power), 10 GNDP (power), 11 GNDP (power), 12 GNDP (power), 13 GNDP (power), 14 GNDP (power), 15 GNDP (power), 16 GNDP (power), 17 GNDP (power), 18 GNDP (power), 19 VEE (power), 20 VEE (power), 21 VEE (power), 22 VEE (power), 23 VEE (power), 24 VEE (power), 25 VEE (power), 26 VEE (power), 27 VEE (power), 28 VDD (power), 29 VDD (power), 30 VEE (power), 31 VEE (power), 32 RLIM (power), 33 FBVEE, 34 FBVDD, 35 VEEA (power), 36 VEE (power)

## CMP-0091185-1
designator MP?, comment CR201-50VE
Heat Sinks Aluminum heatsink 50mmdegreased; Manufacturer: Ohmite; AEC Qualified: No; Natural Thermal Resistance: 3.3°C/W; SizeZ_mm: 75mm; Mating Package: TO-247/TO-264
footprint FP-CR201-50VE_PTH_HEATSINKS_34MM0_50MM0-MFG
pins: 1 MNT_1, 2 MNT_2

## CMP-0091347-1
designator K?, comment SHV05-1A85-78D2K
RELAY REED SPST 1A 5V; Manufacturer: Standex-Meder Electronics; Coil Type: Non-Latching; Coil Current_A: 22mA; Coil Power_W: 110mW; Contact Form: SPST-NO; Contact Rating_A: 2.5A; AEC Qualified: No; Coil Resistance: 220Ω; SizeZ_mm: 8.33mm
footprint FP-SHV05-1A85-78D2K_PTH_RELAY_24MM13_6MM22-MFG
pins: 1, 2, 3, 4

## CMP-0091486-2
designator T?, comment 61259
10kW SMPS Transformer, 24:15, 100kHz, 5000VDC Dielectric, 130x90x52mm; Manufacturer: Payton Planar; TaMin_C: -40°C; TaMax_C: +125°C; Ind_H: 15.3µH; Frequency_Fixed: 100-200kHz; AEC Qualified: No; SizeZ_mm: 52mm
footprint FP-61259_PTH_XFRMR_130MM0_90MM0-MFG
pins: 1, 2, 3, 4

## CMP-0091524-1
designator R?, comment WSL36371L500FEA  (value not drawn)
1.5 mOhms ±1% 3W Chip Resistor Nonstandard Anti-Sulfur, Automotive AEC-Q200, Current Sense, Moisture Resistant, Pulse Withstanding Metal Element; Manufacturer: Vishay; Manufacturer: Vishay Dale; Res_ohm: 1.5m; TempCo: 75ppm/°C; AEC Qualified: Yes; AEC Grade: Grade 0; SizeZ_mm: 0.889mm; Value: 1.5m
footprint FP-WSL36371L500FEA_3637-MFG
pins: 1 E1, 2 E2, 3 I1, 4 I2

## CMP-0092023-2
designator U?, comment ISOW1044DFM
Reinforced 5-kVRMS Isolated CAN Transceiver with Integrated lowemissions DC-DC Converter; Manufacturer: Texas Instruments; TJmax_C: +150°C; Max Supply Voltage: 5.5V; AEC Qualified: No; Standoff Height: 0.1mm; Nominal Supply Current: 0.3-124mA; CompType: IC; AEC Category: Q200; TaMax_C: +105°C; SizeZ_mm: 3.55mm; Min Supply Voltage: 1.71V; TaMin_C: -40°C
footprint DFM0020A-MFG
footprint DFM0020A-IPC_C
footprint DFM0020A-IPC_B
footprint DFM0020A-IPC_A
pins: 1 VIO (power), 2 IN (in), 3 TXD (in), 4 STB (in), 5 RXD (in), 6 GND1 (power), 7 NC, 8 EN (in), 9 VDD (power), 10 GND1 (power), 11 GND2 (power), 12 VISOOUT (out), 13 VISOOUT (out), 14 OUT (out), 15 GND2 (power), 16 GND2 (power), 17 GND2 (power), 18 CANL (io), 19 CANH (io), 20 VISOIN (in)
